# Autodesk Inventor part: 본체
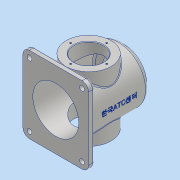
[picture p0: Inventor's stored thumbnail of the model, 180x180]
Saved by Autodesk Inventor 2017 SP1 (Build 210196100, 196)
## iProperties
Part Number: 본체
Material: 알루미늄 6061
Document SubType Name: Modeling
Designer: MRC
Density: 2.7 g/cm^3
Appearance: 알루미늄 - 평지
Mass: 1235.53 g
Surface Area: 1067.6 cm^2
Volume: 457.603 cm^3
Author: MRC
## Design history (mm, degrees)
sketch "스케치1"
  geometry: C1 r 50 at (0, 0); 1 further point
  constraints: 1 centre point, 1 coincident
  dimensions: "d0" = 100 diameter of C1
extrude "돌출1" new body sketch "스케치1" stored distance "d1" = 120; taper "d2" = 0 deg
node "작업 평면1"
sketch "스케치2"
  geometry: C1 r 41 at (0, 0); 1 further point
  constraints: 1 centre point, 1 coincident
  dimensions: "d4" = 82 diameter of C1
extrude "돌출2" join sketch "스케치2" stored distance "d5" = 100; taper "d6" = 0 deg
sketch "스케치3"
  geometry: C1 r 41 at (0, 0) reference; C2 r 27 at (0, 0)
  constraints: 1 centre point, 1 coincident
  dimensions: "d7" = 54 diameter of C2
extrude "돌출3" cut sketch "스케치3" distance "d8" = 59; taper "d9" = 0 deg
sketch "스케치4"
  geometry: C1 r 27 at (0, 0) reference; 1 further point
  constraints: 1 vertical alignment
  dimensions: "d10" = 33 distance of point (0, 33) C1.centre
hole "구멍1" sketch "스케치4" at (0, 33) diameter "d11" = 3.242; stored, may be unused: countersink angle "d15" = 90 deg, drill point angle "d17" = 118 deg; dims "d12" = 8, "d13" = 4, "d14" = 2, "d16" = 10
sketch "스케치5"
  geometry: L1 (60, 70)-(-60, 70); L2 (-60, 70)-(-60, -70); L3 (-60, -70)-(60, -70); L4 (60, -70)-(60, 70); L5 (60, 70)-(-60, -70); L6 (-60, 70)-(60, -70); C1 r 50 at (0, 0) reference
  constraints: 12 end point, 2 midpoint, 2 parallel, 1 horizontal, 1 perpendicular
  dimensions: "d21" = 120 distance of L3.end L2.end; "d22" = 140 distance of L2.end L1.end
extrude "돌출4" join sketch "스케치5" distance "d23" = 10; taper "d24" = 0 deg
sketch "스케치7"
  geometry: C1 r 50 at (0, 0) reference; C2 r 41 at (0, 0)
  constraints: 1 centre point, 1 coincident
  dimensions: "d28" = 82 diameter of C2
extrude "돌출6" join sketch "스케치7" distance "d29" = 5; taper "d30" = 0 deg
sketch "스케치8"
  geometry: C1 r 41 at (0, 0) reference; C2 r 27 at (0, 0)
  constraints: 1 centre point, 1 coincident
  dimensions: "d31" = 54 diameter of C2
extrude "돌출7" cut sketch "스케치8" distance "d32" = 50; taper "d33" = 0 deg
sketch "스케치9"
  geometry: C1 r 27 at (0, 0) reference; 1 further point
  constraints: 1 horizontal alignment
  dimensions: "d34" = 33 distance of C1.centre point (-33, 0)
hole "구멍2" sketch "스케치9" at (-33, 0) diameter "d35" = 3.242; stored, may be unused: countersink angle "d39" = 90 deg, drill point angle "d41" = 118 deg; dims "d36" = 8, "d37" = 4, "d38" = 2, "d40" = 10
node "작업 평면2"
sketch "스케치10"
  geometry: L1 (-50, 70)-(-50, -70) reference; L2 (-60, -70)-(-60, 70) reference; 2 further points
  constraints: 1 horizontal alignment, 1 other
  dimensions: "d64" = 66 distance from line of L2 point (6, 0)
feature "엠보싱1" sketch "스케치10" dims "d47" = 0.5, "d48" = 0
fillet "모깎기1" dims "d49" = 12
sketch "스케치11"
  geometry: C1 r 4.5 at (-48, -58); C2 r 4.5 at (48, -58); C3 r 4.5 at (48, 58); C4 r 4.5 at (-48, 58); A1 r 12 centre (-48, 58) between (-48, 70) and (-60, 58) reference; A2 r 12 centre (-48, -58) between (-60, -58) and (-48, -70) reference; A3 r 12 centre (48, -58) between (48, -70) and (60, -58) reference; A4 r 12 centre (48, 58) between (60, 58) and (48, 70) reference
  constraints: 4 centre point, 4 coincident
  dimensions: "d50" = 9 diameter of C1; "d51" = 9 diameter of C2; "d52" = 9 diameter of C3; "d53" = 9 diameter of C4
extrude "돌출8" cut sketch "스케치11" distance "d54" = 50; taper "d55" = 0 deg
chamfer "모따기1" distance "d56" = 1; stored, may be unused: second distance "d57" = 2, angle "d58" = 45 deg
fillet "모깎기2" dims "d59" = 6, "d60" = 3
node "솔리드1"
pattern_circular "원형 패턴1" dims angle "d19" = 360 deg
mirror "미러1"
sketch "스케치12"
  geometry: C1 r 42 at (0, 0); 1 further point
  constraints: 1 centre point, 1 coincident
  dimensions: "d61" = 84 diameter of C1
extrude "돌출5" cut sketch "스케치12" distance "d62" = 112; taper "d63" = 0 deg
pattern_circular "원형 패턴2" dims angle "d43" = 360 deg
other parameters: "d3" = 59, "d45" = 52.5
